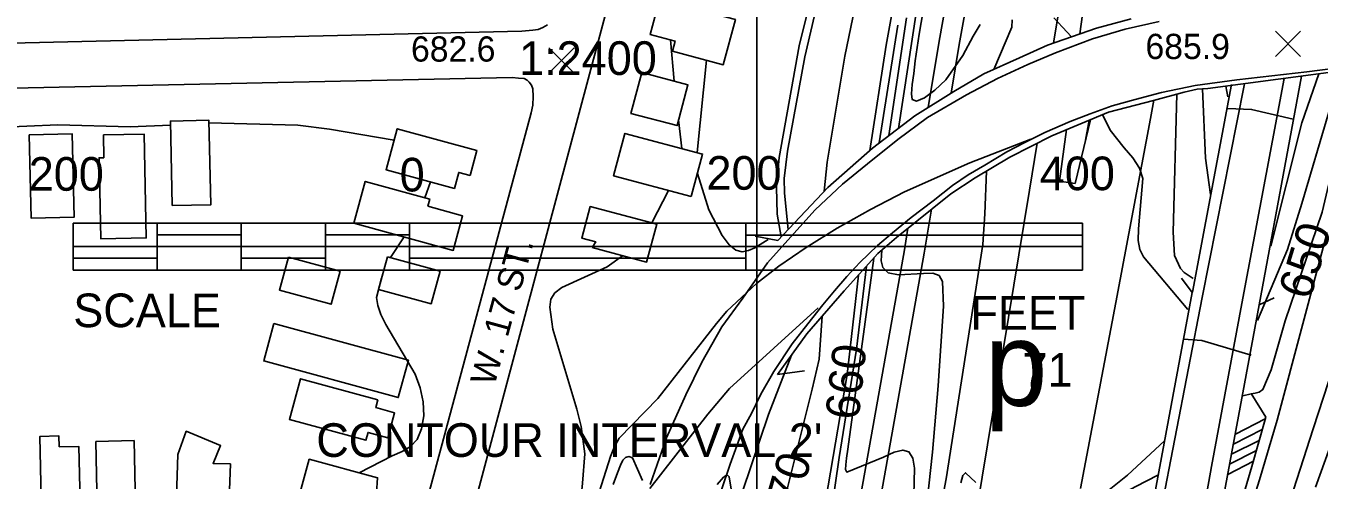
# Model space of a CAD drawing. Extents: x 79600 to 91800, y 75600 to 84400.
# Drawn here: x 85566 to 86334, y 76651 to 76922 of the extents above; entities that cross this region are included whole.
import ezdxf

# ---------------------------------------------------------------- set-up
doc = ezdxf.new("R2010")
doc.units = 0
for name, color, linetype in [('080-085$0$TI_CON_IN', 7, 'Continuous'), ('080-085$0$TI_SCLBAR', 7, 'Continuous'), ('080-090$0$BLDG', 7, 'Continuous'), ('080-090$0$BRIDGE', 7, 'Continuous'), ('080-090$0$GRID', 7, 'Continuous'), ('080-090$0$INDEX', 7, 'Continuous'), ('080-090$0$INDXLBL', 7, 'Continuous'), ('080-090$0$INTER', 7, 'Continuous'), ('080-090$0$INTERSTATE', 7, 'Continuous'), ('080-090$0$ROAD', 7, 'Continuous'), ('080-090$0$ROAD-NAME', 7, 'Continuous'), ('080-090$0$SPOTMARK', 7, 'Continuous'), ('080-090$0$SPOTS', 7, 'Continuous'), ('080-090$0$WALL', 7, 'Continuous')]:
    doc.layers.add(name, color=color, linetype=linetype)

# ---------------------------------------------------------------- blocks, each defined once
blk = doc.blocks.new('080-090$0$SPOTS')
at = {"layer": '080-090$0$SPOTMARK'}
for p, q in [((-0.5, -0.5), (0.5, 0.5)), ((-0.5, 0.5), (0.5, -0.5))]:
    blk.add_line(p, q, dxfattribs=at)

msp = doc.modelspace()

# ---------------------------------------------------------------- linework, layer by layer
at = {"layer": '080-085$0$TI_SCLBAR'}
for p, q in [((85593.57, 76804.31), (86193.57, 76804.31)), ((85593.57, 76776.31), (85593.57, 76804.31)), ((85643.57, 76776.31), (85643.57, 76804.31)), ((85693.57, 76776.31), (85693.57, 76804.31)), ((85743.57, 76776.31), (85743.57, 76804.31)), ((85793.57, 76776.31), (85793.57, 76804.31)), ((85993.57, 76776.31), (85993.57, 76804.31)), ((86193.57, 76776.31), (86193.57, 76804.31)), ((85643.63, 76797.31), (85693.44, 76797.31)), ((85743.49, 76797.31), (85793.3, 76797.31)), ((85993.51, 76797.06), (86193.23, 76797.06)), ((85593.57, 76790.31), (86193.57, 76790.31)), ((85593.58, 76783.39), (85643.39, 76783.39)), ((85693.69, 76783.39), (85743.49, 76783.39)), ((85793.3, 76783.39), (85993.26, 76783.39)), ((85593.57, 76776.31), (86193.57, 76776.31))]:
    msp.add_line(p, q, dxfattribs=at)
at = {"layer": '080-090$0$BLDG'}
for points in [[(85949.82, 76906.5), (85951.41, 76912.48), (85936.58, 76916.42), (85942.13, 76937.3), (85987.24, 76925.3), (85980.1, 76898.45)], [(85931.66, 76893.75), (85959.05, 76886.46), (85952.61, 76862.21), (85925.21, 76869.49)], [(85652.55, 76814.64), (85675.4, 76815.12), (85674.34, 76865.42), (85651.49, 76864.94)], [(85567.59, 76856.75), (85568.62, 76807.25), (85594.19, 76807.79), (85593.15, 76857.29)], [(85611.59, 76856.72), (85611.87, 76843.16), (85609.1, 76843.11), (85610.11, 76794.89), (85637.1, 76795.46), (85635.8, 76857.23)], [(85829.53, 76832.63), (85822.86, 76834.45), (85820.27, 76824.93), (85779.61, 76836.01), (85786.25, 76860.4), (85833.59, 76847.51)], [(85961.08, 76820.13), (85967.77, 76845.29), (85921.58, 76857.57), (85914.89, 76832.4)], [(85804.48, 76814.26), (85805.65, 76818.57), (85767.25, 76829.03), (85760.47, 76804.15), (85819.54, 76788.07), (85825.14, 76808.63)], [(85902.13, 76789.72), (85904.24, 76793.08), (85895.99, 76795.28), (85901, 76814.13), (85940.51, 76803.63), (85934.52, 76781.11)], [(85721.64, 76784.1), (85716.27, 76764.38), (85746.93, 76756.03), (85752.3, 76775.75)], [(85780.41, 76784.3), (85775.12, 76764.87), (85806.45, 76756.34), (85811.74, 76775.77)], [(85712.94, 76744.52), (85706.89, 76722.28), (85786.9, 76700.49), (85792.95, 76722.73)], [(85774.75, 76699.16), (85773.49, 76694.52), (85784.7, 76691.47), (85780.67, 76676.64), (85768.91, 76679.84), (85767.63, 76675.15), (85722.16, 76687.54), (85728.74, 76711.69)], [(85655.91, 76666.66), (85660.86, 76680.52), (85681.27, 76671.94), (85676.84, 76661.4), (85687.14, 76661.06), (85686.62, 76645.38), (85679.28, 76645.62), (85678.29, 76615.94), (85654.26, 76616.74)], [(85585.35, 76671.15), (85585.22, 76677.69), (85573.91, 76677.45), (85575.28, 76612.94), (85598.32, 76613.43), (85597.09, 76671.4)], [(85607.04, 76674.42), (85608.29, 76615.55), (85631.1, 76616.03), (85629.86, 76674.9)], [(85774.03, 76643.6), (85777.94, 76642.54), (85774.18, 76628.72), (85769.18, 76630.09), (85768.79, 76628.65), (85727.44, 76639.91), (85733.97, 76663.88), (85774.61, 76652.82)]]:
    msp.add_lwpolyline(points, close=True, dxfattribs=at)
at = {"layer": '080-090$0$BRIDGE'}
for p, q in [((86222.49, 76925.81), (86201.91, 76920.17)), ((86201.91, 76920.17), (86172.82, 76910.09)), ((86172.82, 76910.09), (86156.22, 76902.59)), ((86268.08, 76884.35), (86457.24, 76909.32)), ((86156.22, 76902.59), (86134.89, 76892.95)), ((86134.89, 76892.95), (86117.14, 76882.56)), ((86117.14, 76882.56), (86093.93, 76868.1)), ((86235.79, 76877.27), (86253.98, 76882.07)), ((86253.98, 76882.07), (86261.71, 76883.89)), ((86261.71, 76883.89), (86268.08, 76884.35)), ((86209.04, 76870.2), (86235.79, 76877.27)), ((86093.93, 76868.1), (86068.71, 76848.82)), ((86175.27, 76856.16), (86209.04, 76870.2)), ((86150.33, 76843.41), (86175.27, 76856.16)), ((86068.71, 76848.82), (86042.17, 76825.41)), ((86129.77, 76831.15), (86150.33, 76843.41)), ((86150.33, 76843.41), (86150.33, 76843.41)), ((86042.17, 76825.41), (86012.47, 76794.01)), ((86115.37, 76821.65), (86129.77, 76831.15)), ((86082.98, 76795.7), (86115.37, 76821.65)), ((86332.05, 76647.16), (86390.34, 76809.26)), ((86012.47, 76794.01), (85999.08, 76796.43)), ((86071.99, 76786.14), (86082.98, 76795.7)), ((86082.98, 76795.7), (86082.98, 76795.7)), ((86051.89, 76764.05), (86071.99, 76786.14)), ((86252.39, 76771.49), (86258.77, 76762.95)), ((86029.68, 76738.4), (86051.89, 76764.05)), ((86258.77, 76762.95), (86226.62, 76590.06)), ((86298.54, 76755.69), (86275.13, 76629.48)), ((86307.47, 76759.85), (86298.54, 76755.69)), ((86012.39, 76714.3), (86029.68, 76738.4)), ((86028.31, 76716.36), (86012.39, 76714.3)), ((86293.85, 76702.86), (86302.5, 76688.88)), ((86302.5, 76688.88), (86294.29, 76659.51)), ((86294.29, 76659.51), (86282.46, 76619.39))]:
    msp.add_line(p, q, dxfattribs=at)
at = {"layer": '080-090$0$GRID'}
msp.add_line((86000, 80000), (86000, 76000), dxfattribs=at)
at = {"layer": '080-090$0$INDEX'}
msp.add_line((86279.9, 76654.85), (86295.21, 76662.78), dxfattribs=at)
for points in [[(86018.65, 76800.55), (86016.49, 76821.97), (86016.33, 76830.73), (86018.34, 76847.07), (86028.57, 76903.21), (86039.31, 76949.18), (86048.34, 76990.45), (86086.42, 77208.13), (86092.47, 77250.2), (86096.81, 77275.28), (86121.04, 77367.24), (86126.16, 77387.72), (86142.26, 77486.18), (86147.79, 77517.82), (86157.15, 77554.91), (86178.26, 77654.29), (86209.61, 77810.75), (86229.26, 77929.48)], [(86040.08, 76823.19), (86041.87, 76840.5), (86052.39, 76903.52), (86067.67, 76977.57), (86113.23, 77231.03), (86118.85, 77262.29), (86145.13, 77371.79), (86171.69, 77508.38), (86186.15, 77573.63), (86214.31, 77715.96), (86229.98, 77798.2), (86250.86, 77930)], [(86067.16, 76847.46), (86076.86, 76910.04), (86103.11, 77054.59)], [(86288.94, 76701.48), (86293.86, 76702.78), (86296.19, 76703.2), (86298.52, 76703.63), (86300.85, 76705.23), (86305.82, 76717.07), (86314.1, 76746.21), (86336.09, 76810.76), (86356.09, 76895.85)], [(86055.64, 76435.99), (86028.56, 76445.33), (86023.57, 76446.72), (86020.49, 76448.56), (86018.9, 76451.8), (86018.7, 76464.25), (86029.35, 76562.77), (86035.44, 76607.31), (86053.68, 76714.26), (86060.35, 76773.34)], [(85927.79, 76000), (85928.25, 76034.78), (85929.01, 76053.66), (85940.47, 76166.37), (85942.89, 76204.74), (85943.99, 76214.52), (85945.97, 76224.17), (85952.28, 76242.79), (85964.45, 76269.22), (85970.66, 76287.18), (85974.58, 76305.93), (85979.24, 76352.91), (85985.21, 76393.65), (85995.65, 76517.22), (85998.04, 76546.01), (86001.89, 76573.13), (86010.57, 76615.88), (86032.95, 76705.43), (86037.04, 76723.42), (86038.81, 76748.94)], [(85981.27, 76614.16), (86007, 76690.42), (86020.63, 76725.79)], [(86200.56, 76638.54), (86220.36, 76654.36), (86242.26, 76674.84)], [(86121.3, 76649.76), (86122.51, 76654.18), (86124, 76655.77), (86130.13, 76649.95)], [(85976.42, 76648.86), (85980.22, 76653.17), (85982.4, 76654.64), (85983.63, 76653.47), (85984.91, 76644.82)]]:
    msp.add_lwpolyline(points, dxfattribs=at)
at = {"layer": '080-090$0$INTER'}
for p, q in [((85948.62, 76913.22), (85950.92, 76888.63)), ((85964.47, 76846.17), (85970.13, 76901.1)), ((86279.91, 76879.33), (86278.78, 76885.76)), ((85953.51, 76865.63), (85955.43, 76848.57)), ((85802.71, 76819.37), (85806.05, 76828.81)), ((85947.57, 76823.72), (85937.64, 76804.39)), ((85782.26, 76783.79), (85790.35, 76796.02)), ((86302.22, 76687.89), (86284.53, 76678.72)), ((86300.42, 76681.43), (86283.37, 76672.75)), ((86282.21, 76666.78), (86298.63, 76675.05)), ((86281.06, 76660.82), (86296.98, 76669.13))]:
    msp.add_line(p, q, dxfattribs=at)
for points in [[(86014.47, 76796.13), (86012.04, 76809.6), (86011.63, 76825.73), (86013.33, 76843.32), (86025.1, 76909.68), (86034.84, 76949.18), (86043.97, 76991.53), (86065.15, 77110.62), (86082.64, 77213.75), (86088.59, 77257.22), (86093.21, 77282.11), (86117.63, 77370.99), (86122.3, 77390.87), (86138.54, 77494), (86144.18, 77524.9), (86152.59, 77556.71), (86169.99, 77636.95), (86203.37, 77802.84), (86218.03, 77884.08), (86224.57, 77929.37)], [(86097.88, 76950.15), (86084.14, 76860.62)], [(86102.15, 76949.17), (86096.54, 76916.54), (86094.22, 76900.74), (86093.25, 76893.27), (86092.42, 76886.61), (86091.91, 76881.23), (86092.42, 76877.74), (86094.83, 76876.8), (86099.62, 76878.84), (86105.87, 76883.33), (86112.3, 76889.52), (86122.38, 76903.84), (86128.67, 76915.46), (86132.8, 76922.42)], [(86089.03, 76926.32), (86078.48, 76856.29)], [(86151.75, 76925.06), (86151.62, 76920.84), (86140.87, 76895.65)], [(86187.07, 76915.02), (86181.73, 76920.87), (86176.64, 76926.27)], [(86083.81, 76922.07), (86072.8, 76851.95)], [(86349.37, 76895.08), (86340.07, 76870.3), (86324.01, 76815.96), (86315.35, 76788.59), (86297.63, 76746.34)], [(86334.15, 76893.07), (86324, 76863.87), (86305.44, 76790.47)], [(86259.27, 76771.32), (86254.11, 76774.81), (86251.83, 76777.21), (86248.24, 76784.99), (86247.41, 76798.85), (86249.6, 76880.92)], [(86269.69, 76821.33), (86266.78, 76842.97), (86264.86, 76884.12)], [(86279.96, 76872.51), (86294.05, 76871.83), (86318.82, 76866.03)], [(85651.55, 76862.41), (85627.5, 76861.46), (85584.55, 76862.71), (85529.08, 76860.25), (85453.75, 76859.79), (85427.07, 76860.32), (85390.29, 76863.66), (85336.79, 76866.23), (85319.2, 76866.34), (85273.58, 76861.72), (85254.56, 76860.48), (85179.09, 76861.41), (85150.54, 76861.68), (85118.58, 76865.26), (85093.66, 76865.47), (85000, 76860.15)], [(85784.38, 76853.53), (85746, 76860.18), (85727.26, 76862.44), (85674.38, 76863.96)], [(86205.57, 76868.76), (86210.03, 76859.58), (86218.41, 76849.08), (86223.51, 76843.14), (86227.5, 76837.01), (86229.36, 76830.77), (86226.78, 76800.87), (86226.64, 76793.86), (86227.59, 76788.53), (86229.78, 76784.11), (86256.21, 76752.9)], [(85892.93, 76693.55), (85895.6, 76683.38), (85897.87, 76667.04), (85896.36, 76649.69), (85895.64, 76641.38), (85895.96, 76633.69), (85897.17, 76627.9), (85898.92, 76625.5), (85900.92, 76627.51), (85913.06, 76665.38), (85915.37, 76671.33), (85918.11, 76676.32), (85941.09, 76699.95), (85976.01, 76744.51), (85982.15, 76751.83), (85999.79, 76768.43), (86013.14, 76778.65), (86029.35, 76789.81), (86047.71, 76801.26), (86067.49, 76812.4), (86087.82, 76822.83), (86126.54, 76840.18), (86162.91, 76854.17)], [(86006.72, 76794.58), (85998.87, 76789.55), (85995.13, 76787.92), (85991.38, 76787.26), (85987.58, 76788.18), (85983.58, 76791.3), (85979.34, 76796.93), (85971.55, 76812.1), (85964.69, 76833.69)], [(86136.62, 76835.23), (86135.58, 76809.7), (86134.34, 76791.62), (86112.52, 76652.23), (86066.66, 76407.81), (86054.22, 76342.6), (86048.15, 76314.11), (86025.34, 76231.14), (86017.86, 76203.32), (86000.08, 76110.09), (85993.61, 76072.06), (85983.93, 76000)], [(86074.29, 76788.14), (86073.95, 76781.85), (86074.88, 76777.88), (86078.05, 76774.79), (86084.13, 76773.6), (86099.13, 76774.33), (86104.68, 76774.42), (86108.35, 76773.14), (86110.4, 76769.62), (86111.02, 76754.93), (86107.86, 76707.42), (86104.39, 76668.09), (86101.33, 76638.92), (86058.91, 76409.11), (86045.97, 76341.72), (86041.99, 76322.66), (86028.91, 76279.46)], [(85920.26, 76784.9), (85911.09, 76778.22), (85884.19, 76766.01), (85879.93, 76762.77), (85877.67, 76758.98), (85876.98, 76754.2), (85878.74, 76741.21), (85892.93, 76693.55)], [(86065.12, 76778.58), (86059.27, 76729.22), (86048.91, 76664.87), (86041.95, 76616.93), (86036.83, 76577.6), (86036.03, 76570.6), (86035.36, 76564.55), (86035, 76559.81), (86035.71, 76556.66), (86038.38, 76555.32), (86057.48, 76560.22), (86063.84, 76562.51), (86068.87, 76563.46), (86072.14, 76561.84), (86073.42, 76556.99), (86072.25, 76540.44)], [(86069.6, 76783.51), (86054.11, 76669.89), (86053.37, 76664.52), (86052.85, 76660.48), (86052.64, 76657.65), (86053.48, 76656.23), (86075.34, 76665.17), (86081.61, 76667.95), (86086.71, 76669.26), (86090.45, 76668.32), (86092.73, 76664.56), (86093.76, 76658.51), (86093.25, 76642.55), (86075.71, 76546.96)], [(85763.66, 76655.8), (85783.35, 76665.85), (85789.15, 76668.45), (85794.17, 76671.4), (85798.13, 76675.66), (85800.77, 76681.89), (85801.99, 76689.59), (85801.73, 76697.95), (85799.99, 76706.3), (85796.98, 76714.46), (85779.52, 76743.97), (85776.5, 76749.97), (85774.66, 76755.31), (85773.98, 76760.04), (85776.95, 76771.58)], [(85936.36, 76646.45), (85970.95, 76690.71), (85983.79, 76705.86), (86036.52, 76753.96)], [(86253.62, 76735.19), (86264.56, 76734.4), (86293.78, 76725.69)], [(85914.63, 76648.87), (85917.16, 76655.72), (85918.99, 76660.39), (85920.45, 76663.23), (85921.98, 76664.8), (85923.9, 76665.45), (85926.06, 76664.72), (85932.05, 76651.17)], [(86238.32, 76654.45), (86225.3, 76647.6), (86213.22, 76641.06), (86207.84, 76637.22), (86203.35, 76632.18), (86199.97, 76625.51), (86190.67, 76590.35), (86167.86, 76488.27), (86139.62, 76349.95), (86130.4, 76304.64), (86128.58, 76296.71), (86126, 76290.4), (86121.84, 76286.94), (86115.58, 76287.19), (86107.97, 76290.35), (86100.05, 76295.26), (86092.72, 76300.92), (86086.26, 76307.15), (86072.9, 76326.34), (86070.07, 76328.15), (86067.7, 76324.9), (86018.66, 76104.64), (86012.32, 76076.24), (86000.08, 76000)]]:
    msp.add_lwpolyline(points, dxfattribs=at)
at = {"layer": '080-090$0$INTERSTATE'}
for p, q in [((86132.98, 77048.35), (86108.46, 76912.46)), ((86144.8, 77046.26), (86120.28, 76910.41)), ((86181.48, 76942.36), (86176.4, 76911.33)), ((86191.98, 76916.73), (86194.99, 76938.55)), ((86108.46, 76912.46), (86101.87, 76873.04)), ((86120.28, 76910.41), (86115.45, 76881.5)), ((86264.68, 76760.09), (86289.6, 76886)), ((86313.55, 76890.35), (86288.31, 76756.54)), ((86289.6, 76886), (86289.83, 76887.22)), ((86236.07, 76877.35), (86234.05, 76866.5)), ((86198.26, 76865.72), (86189.14, 76827.86)), ((86197.55, 76865.43), (86195.35, 76853.66)), ((86234.05, 76866.5), (86213.39, 76757)), ((86179.88, 76829.11), (86184.13, 76859.84)), ((86166.64, 76851.75), (86162.07, 76823.84)), ((86189.14, 76827.86), (86179.88, 76829.11)), ((86162.07, 76823.84), (86127.4, 76613.05)), ((86103.9, 76812.46), (86099.54, 76786.38)), ((86089.86, 76801.21), (86087.72, 76788.43)), ((86338.94, 76798.69), (86309.26, 76687.11)), ((86087.72, 76788.43), (86046.2, 76555.44)), ((86099.54, 76786.38), (86058.01, 76553.35)), ((86364.8, 76786.8), (86330.64, 76681.94)), ((86213.39, 76757), (86192.45, 76646.53)), ((86232.64, 76594.54), (86264.68, 76760.09)), ((86288.31, 76756.54), (86270.34, 76659.6)), ((86309.26, 76687.11), (86298.74, 76651.55)), ((86330.64, 76681.94), (86302.71, 76594.57)), ((86270.34, 76659.6), (86247.5, 76534.49)), ((86298.74, 76651.55), (86289.57, 76622.61))]:
    msp.add_line(p, q, dxfattribs=at)
at = {"layer": '080-090$0$ROAD'}
for p, q in [((85918.05, 76958.04), (85820.94, 76594.91)), ((86218.94, 76919.63), (86239.23, 76924.16)), ((85860.25, 76918.35), (85000, 76898.13)), ((85866.91, 76918.94), (85860.25, 76918.35)), ((85870.1, 76919.45), (85866.91, 76918.94)), ((85872.75, 76920.52), (85870.1, 76919.45)), ((85875.54, 76922.27), (85872.75, 76920.52)), ((86199.6, 76913.83), (86218.94, 76919.63)), ((86326.84, 76894.15), (86499.33, 76917.4)), ((86177.46, 76905.59), (86199.6, 76913.83)), ((86161.01, 76898.64), (86177.46, 76905.59)), ((86143.15, 76890.33), (86161.01, 76898.64)), ((86285.36, 76889.39), (86326.84, 76894.15)), ((85000, 76872.34), (85854.57, 76890.88)), ((85854.57, 76890.88), (85858.3, 76890.55)), ((85858.3, 76890.55), (85861.76, 76890.22)), ((85861.76, 76890.22), (85863.54, 76889.22)), ((85863.54, 76889.22), (85864.77, 76888.1)), ((85864.77, 76888.1), (85866.13, 76886.27)), ((85866.13, 76886.27), (85866.93, 76884.05)), ((86124.73, 76880.64), (86143.15, 76890.33)), ((86240.52, 76881.91), (86260.52, 76886.03)), ((86260.52, 76886.03), (86285.36, 76889.39)), ((85867.13, 76879.47), (85866.92, 76874.35)), ((85866.93, 76884.05), (85867.13, 76879.47)), ((86101.39, 76867.15), (86124.73, 76880.64)), ((86224.8, 76877.72), (86240.52, 76881.91)), ((85866.92, 76874.35), (85865.88, 76869.8)), ((86198.09, 76869.26), (86211.18, 76874.05)), ((86211.18, 76874.05), (86224.8, 76877.72)), ((85865.88, 76869.8), (85796.7, 76612.87)), ((86083.74, 76853.99), (86101.39, 76867.15)), ((86171.19, 76858.18), (86186.24, 76864.6)), ((86186.24, 76864.6), (86198.09, 76869.26)), ((86159.33, 76852.27), (86171.19, 76858.18)), ((86065.79, 76839.58), (86083.74, 76853.99)), ((86148.58, 76846.62), (86159.33, 76852.27)), ((86050.93, 76827.35), (86065.79, 76839.58)), ((86135.44, 76838.65), (86148.58, 76846.62)), ((86116.28, 76826.62), (86125.65, 76832.99)), ((86125.65, 76832.99), (86135.44, 76838.65)), ((86034.77, 76812.23), (86050.93, 76827.35)), ((86104.78, 76817.52), (86116.28, 76826.62)), ((86091.75, 76807.61), (86104.78, 76817.52)), ((86020.26, 76796.11), (86034.77, 76812.23)), ((86080.67, 76798.5), (86091.75, 76807.61)), ((86006.31, 76780.67), (86020.26, 76796.11)), ((86071.83, 76790.88), (86080.67, 76798.5)), ((86061.29, 76780.8), (86071.83, 76790.88)), ((85991.73, 76759.71), (86006.31, 76780.67)), ((86053.55, 76772.47), (86061.29, 76780.8)), ((86046.21, 76764), (86053.55, 76772.47)), ((86039.3, 76755.66), (86046.21, 76764)), ((85979.28, 76742.59), (85991.73, 76759.71)), ((86030.4, 76744.44), (86039.3, 76755.66)), ((85967.32, 76721.59), (85979.28, 76742.59)), ((86021.08, 76732.53), (86030.4, 76744.44)), ((86010.16, 76715.94), (86021.08, 76732.53)), ((85957.74, 76702.07), (85967.32, 76721.59)), ((86002.48, 76702.49), (86010.16, 76715.94)), ((85946.41, 76676.49), (85957.74, 76702.07)), ((85996.76, 76690.95), (86002.48, 76702.49)), ((85991.64, 76681.75), (85996.76, 76690.95)), ((85988.88, 76673.9), (85991.64, 76681.75)), ((85936.57, 76648.8), (85946.41, 76676.49)), ((85984.25, 76660.95), (85988.88, 76673.9)), ((85979.03, 76645.66), (85984.25, 76660.95))]:
    msp.add_line(p, q, dxfattribs=at)
at = {"layer": '080-090$0$WALL'}
for p, q in [((86258.89, 76763.13), (86282.06, 76886.75)), ((86298.6, 76755.69), (86323.83, 76891.71))]:
    msp.add_line(p, q, dxfattribs=at)

# ---------------------------------------------------------------- block references
at = {"layer": '080-090$0$SPOTMARK', "xscale": 15, "yscale": 15}
for p in [(86315.71, 76910.88), (85883.88, 76900.93)]:
    msp.add_blockref('080-090$0$SPOTS', p, dxfattribs=at)

# ---------------------------------------------------------------- texts
at = {"layer": '080-085$0$TI_CON_IN'}
msp.add_text("CONTOUR INTERVAL 2'", height=20, dxfattribs=at).set_placement((85738.18, 76665.23))
at = {"layer": '080-085$0$TI_SCLBAR'}
for s, p in [('1:2400', (85858.74, 76892.37)), ('200', (85567.25, 76823.52)), ('0', (85787.73, 76823.09)), ('200', (85970.07, 76824.12)), ('400', (86168.2, 76823.83)), ('SCALE', (85593.73, 76742.38)), ('FEET', (86126.93, 76740.92))]:
    msp.add_text(s, height=20, dxfattribs=at).set_placement(p)
at = {"layer": '080-090$0$INDXLBL'}
for s, rotation, p in [('650', 73.06616, (86328.8, 76757.95)), ('660', 83.8274, (86060.51, 76686.77)), ('670', 73.84957, (86020.46, 76621.3))]:
    msp.add_text(s, height=20, rotation=rotation, dxfattribs=at).set_placement(p)
at = {"layer": '080-090$0$ROAD-NAME'}
msp.add_text('W. 17 ST.', height=15, rotation=74.73552, dxfattribs=at).set_placement((85843.97, 76706.8))
for s, height, p in [('p', 50, (86135.54, 76695.6)), ('71', 20, (86157.92, 76707.03))]:
    msp.add_text(s, height=height, dxfattribs=at).set_placement(p)
at = {"layer": '080-090$0$SPOTS'}
for s, p in [('685.9', (86231.01, 76901.83)), ('682.6', (85794.45, 76900.31))]:
    msp.add_text(s, height=15, dxfattribs=at).set_placement(p)

doc.saveas('drawing.dxf')
